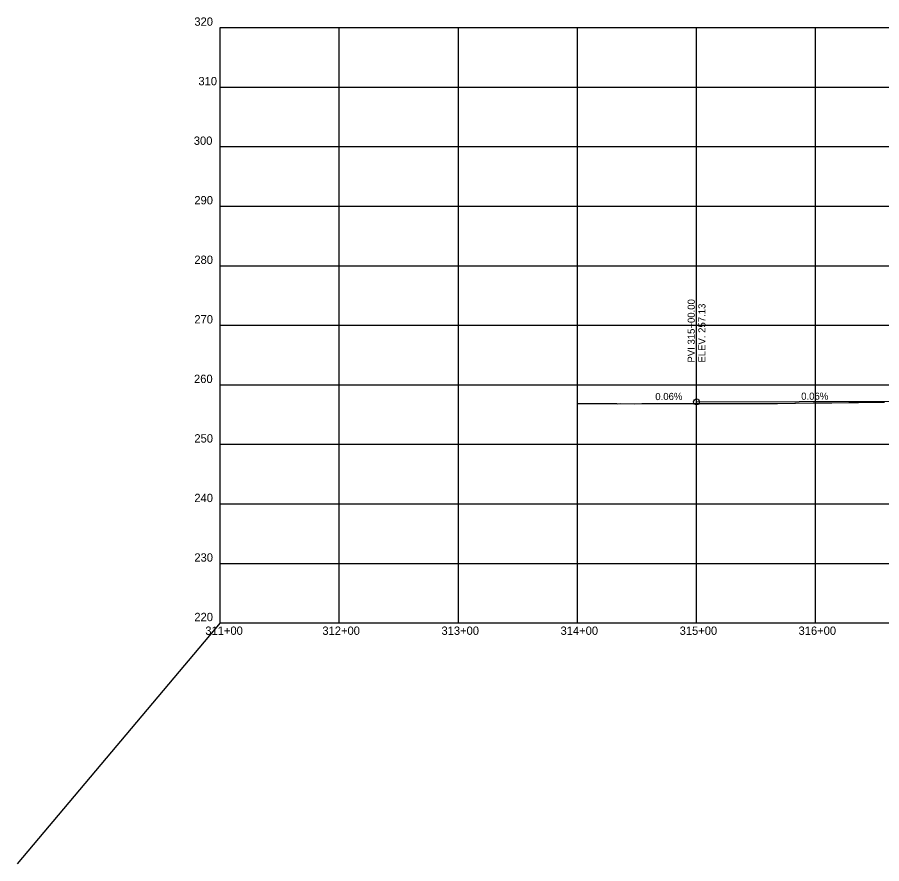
# Model space of a CAD drawing. Extents: x 881054 to 892094, y 1562235 to 1563136.
# Drawn here: x 881054 to 881780, y 1562424 to 1563135 of the extents above; entities that cross this region are included whole.
import ezdxf

# ---------------------------------------------------------------- set-up
doc = ezdxf.new("R2010")
doc.units = 0
for name, color, linetype in [('R_Axis', 7, 'Continuous'), ('R_Axis Annot', 7, 'Continuous'), ('R_Exist Surface', 7, 'Continuous'), ('R_Grid', 7, 'Continuous'), ('R_Horz Alg Annot', 7, 'Continuous'), ('R_No Plot', 7, 'Continuous'), ('R_Vert Alg', 7, 'Continuous'), ('R_Vert Alg Annot', 7, 'Continuous')]:
    doc.layers.add(name, color=color, linetype=linetype)

msp = doc.modelspace()

# ---------------------------------------------------------------- linework, layer by layer
at = {"layer": 'R_Axis'}
for q in [(881224.24, 1563126.14), (882724.24, 1562626.14)]:
    msp.add_line((881224.24, 1562626.14), q, dxfattribs=at)
at = {"layer": 'R_Exist Surface'}
msp.add_lwpolyline([(881524.24, 1562810.46), (881526.2, 1562810.47), (881527.14, 1562810.47), (881527.14, 1562810.47), (881528.04, 1562810.47), (881542.14, 1562810.45), (881542.14, 1562810.45), (881556.61, 1562810.29), (881557.14, 1562810.29), (881557.14, 1562810.29), (881557.86, 1562810.28), (881560.03, 1562810.29), (881572.14, 1562810.28), (881572.14, 1562810.28), (881578.31, 1562810.29), (881587.14, 1562810.29), (881587.14, 1562810.29), (881599.07, 1562810.31), (881602.14, 1562810.31), (881602.14, 1562810.31), (881606.74, 1562810.34), (881617.15, 1562810.42), (881617.15, 1562810.41), (881630.91, 1562810.41), (881632.15, 1562810.41), (881632.15, 1562810.41), (881632.27, 1562810.41), (881646.62, 1562810.48), (881647.15, 1562810.48), (881647.15, 1562810.48), (881662.14, 1562810.46), (881662.15, 1562810.46), (881662.15, 1562810.46), (881662.24, 1562810.46), (881677.15, 1562810.41), (881677.15, 1562810.41), (881689.7, 1562810.46), (881692.15, 1562810.47), (881692.15, 1562810.47), (881706.8, 1562810.67), (881707.15, 1562810.68), (881707.15, 1562810.68), (881707.35, 1562810.68), (881722.16, 1562810.87), (881722.31, 1562810.87), (881737.16, 1562810.99), (881737.16, 1562810.99), (881737.71, 1562811), (881752.16, 1562811.14), (881752.16, 1562811.13), (881753.87, 1562811.15), (881760.26, 1562811.32), (881767.16, 1562811.44), (881767.16, 1562811.44), (881776.99, 1562811.5), (881782.16, 1562811.54)], dxfattribs=at)
at = {"layer": 'R_Grid'}
for p, q in [((881224.24, 1563126.14), (882724.24, 1563126.14)), ((881224.24, 1563126.14), (882724.24, 1563126.14)), ((881324.24, 1562626.14), (881324.24, 1563126.14)), ((881424.24, 1562626.14), (881424.24, 1563126.14)), ((881524.24, 1562626.14), (881524.24, 1563126.14)), ((881624.24, 1562626.14), (881624.24, 1563126.14)), ((881724.24, 1562626.14), (881724.24, 1563126.14)), ((881224.24, 1563076.14), (882724.24, 1563076.14)), ((881224.24, 1563026.14), (882724.24, 1563026.14)), ((881224.24, 1562976.14), (882724.24, 1562976.14)), ((881224.24, 1562926.14), (882724.24, 1562926.14)), ((881224.24, 1562876.14), (882724.24, 1562876.14)), ((881224.24, 1562826.14), (882724.24, 1562826.14)), ((881224.24, 1562776.14), (882724.24, 1562776.14)), ((881224.24, 1562726.14), (882724.24, 1562726.14)), ((881224.24, 1562676.14), (882724.24, 1562676.14))]:
    msp.add_line(p, q, dxfattribs=at)
at = {"layer": 'R_No Plot'}
msp.add_line((881224.24, 1562626.14), (881053.85, 1562423.97), dxfattribs=at)
at = {"layer": 'R_Vert Alg'}
msp.add_line((881624.24, 1562811.77), (881824.24, 1562812.37), dxfattribs=at)
at = {"layer": 'R_Vert Alg Annot'}
for p, q in [((881624.24, 1562841.77), (881624.24, 1562925.77)), ((881624.24, 1562811.77), (881624.24, 1562841.77))]:
    msp.add_line(p, q, dxfattribs=at)
msp.add_circle((881624.24, 1562811.77), 2.5, dxfattribs=at)

# ---------------------------------------------------------------- texts
at = {"layer": 'R_Axis Annot'}
for s, height, p in [('320', 7, (881202.55, 1563127.64)), ('320', 7, (881202.55, 1563127.64)), ('310', 7, (881205.95, 1563077.64)), ('300', 7, (881202.08, 1563027.64)), ('290', 7, (881202.55, 1562977.64)), ('280', 7, (881202.55, 1562927.64)), ('270', 7, (881202.55, 1562877.64)), ('260', 7, (881202.27, 1562827.64)), ('250', 7, (881202.55, 1562777.64)), ('240', 7, (881202.55, 1562727.64)), ('230', 7, (881202.55, 1562677.64)), ('220', 7, (881202.55, 1562627.64)), ('-', 0.0001, (881224.24, 1562626.14)), ('311+00', 7, (881211.75, 1562616.14)), ('312+00', 7, (881310.05, 1562616.14)), ('313+00', 7, (881410.05, 1562616.14)), ('314+00', 7, (881510.05, 1562616.14)), ('315+00', 7, (881610.05, 1562616.14)), ('316+00', 7, (881709.9, 1562616.14))]:
    msp.add_text(s, height=height, dxfattribs=at).set_placement(p)
at = {"layer": 'R_Horz Alg Annot'}
msp.add_text('0.06%', height=6, rotation=0.39838, dxfattribs=at).set_placement((881589.62, 1562813.26))
at = {"layer": 'R_Vert Alg Annot'}
for s, rotation, p in [('PVI 315+00.00', 90, (881622.74, 1562844.77)), ('ELEV. 257.13', 90, (881631.74, 1562844.77)), ('0.06%', 0.17189, (881712.12, 1562813.54))]:
    msp.add_text(s, height=6, rotation=rotation, dxfattribs=at).set_placement(p)

doc.saveas('drawing.dxf')
